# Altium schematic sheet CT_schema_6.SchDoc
size 252 x 159 mm
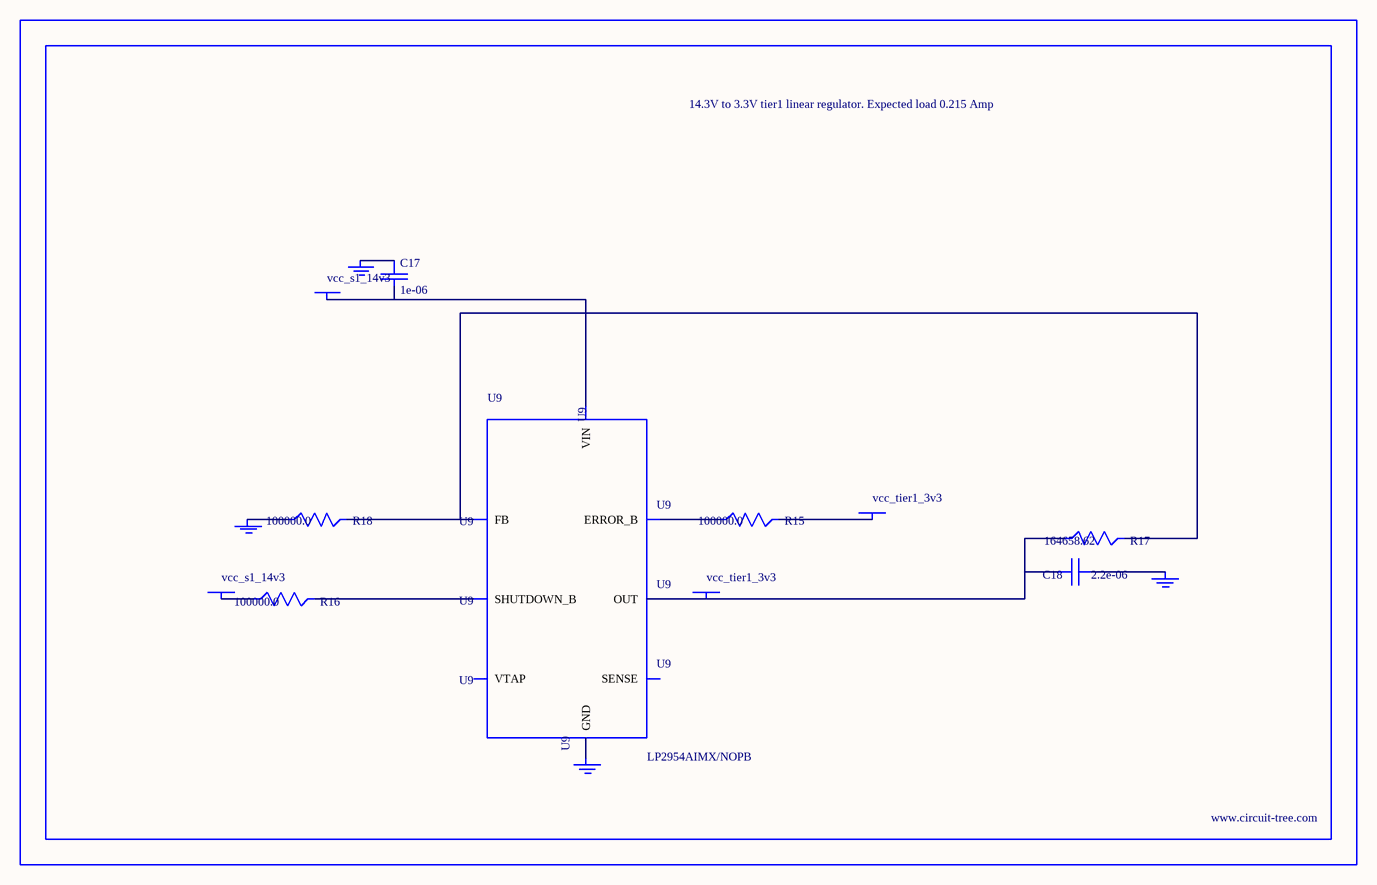
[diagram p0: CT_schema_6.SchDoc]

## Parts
BORDER5  (no value)
C17  1e-06  [EXV-9B]
C18  2.2e-06  [EXV-9B]
GND_INSTANCE_5_0  (no value)
GND_INSTANCE_5_1  (no value)
GND_INSTANCE_5_2  (no value)
GND_INSTANCE_5_3  (no value)
POWER_INSTANCE_5_0  vcc_s1_14v3
POWER_INSTANCE_5_1  vcc_tier1_3v3
POWER_INSTANCE_5_2  vcc_s1_14v3
POWER_INSTANCE_5_3  vcc_tier1_3v3
R15  100000.0  [R0603]
R16  100000.0  [R0603]
R17  164658.62  [R0603]
R18  100000.0  [R0603]
U9  LP2954AIMX/NOPB  [LP2954]

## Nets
NetC17_1: C17.1 GND_INSTANCE_5_2.0(GND)
NetC17_2: C17.2 POWER_INSTANCE_5_2.0(PWR) U9.8(VIN)
NetC18_1: C18.1 GND_INSTANCE_5_0.0(GND)
NetC18_2: C18.2 POWER_INSTANCE_5_3.0(PWR) R17.1 U9.1(OUT)
NetGND_INSTANCE_5_1_0: GND_INSTANCE_5_1.0(GND) R18.1
NetGND_INSTANCE_5_3_0: GND_INSTANCE_5_3.0(GND) U9.4(GND)
NetPOWER_INSTANCE_5_0_0: POWER_INSTANCE_5_0.0(PWR) R16.1
NetPOWER_INSTANCE_5_1_0: POWER_INSTANCE_5_1.0(PWR) R15.2
NetR15_1: R15.1 U9.5(ERROR_B)
NetR16_2: R16.2 U9.3(SHUTDOWN_B)
NetR17_2: R17.2 R18.2 U9.7(FB)

Not connected (* = marked no-connect by the designer): U9 2(SENSE) 6(VTAP)

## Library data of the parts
BORDER5 = BORDER_PAGE5
C17 = EDK105M050A9BAA
C18 = EDK225M050A9BAA
GND_INSTANCE_5_0-GND_INSTANCE_5_3 = GND
POWER_INSTANCE_5_0-POWER_INSTANCE_5_3 = PWR
R15 R16 R18 = RC0603JR-07100KL
R17 = R17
